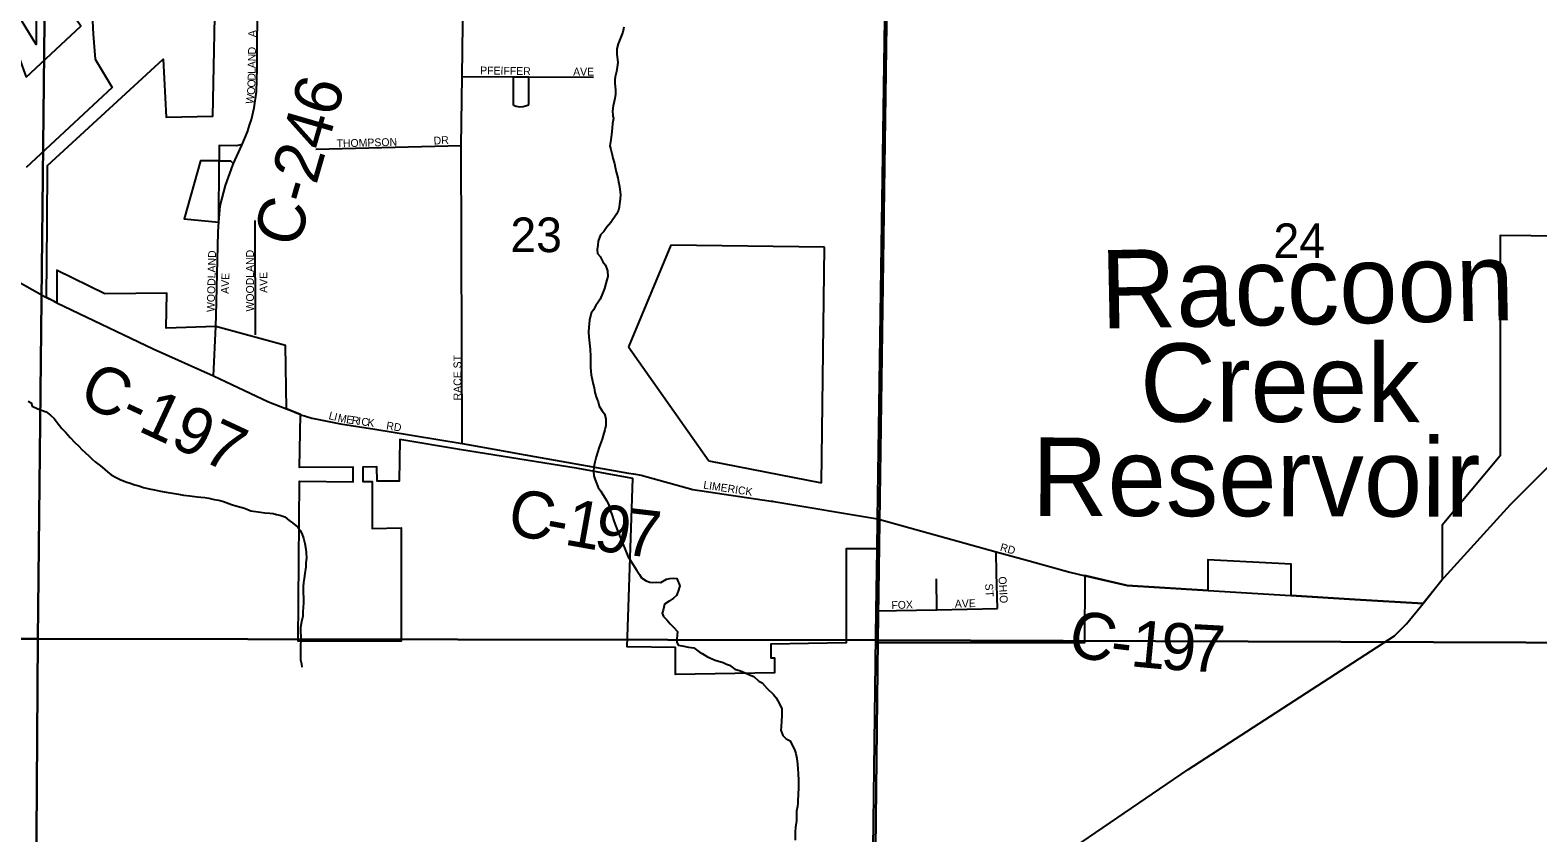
# Model space of a CAD drawing. Extents: x 1588073 to 2013523, y 1090242 to 1357120.
# Drawn here: x 1832450 to 1842074, y 1195862 to 1200987 of the extents above; entities that cross this region are included whole.
import ezdxf

# ---------------------------------------------------------------- set-up
doc = ezdxf.new("R2010")
doc.units = 0
for name, color, linetype in [('GM_X_City_Street', 7, 'Continuous'), ('GM_X_City_Street_Text', 7, 'Continuous'), ('GM_X_Corporation', 7, 'Continuous'), ('GM_X_County_Road', 7, 'Continuous'), ('GM_X_County_Road_Text', 7, 'Continuous'), ('GM_X_Minor_Lake', 7, 'Continuous'), ('GM_X_Minor_Lake_Text', 7, 'Continuous'), ('GM_X_Minor_River', 7, 'Continuous'), ('GM_X_Section', 7, 'Continuous'), ('GM_X_Section_Text', 7, 'Continuous'), ('GM_X_State_Route', 7, 'Continuous')]:
    doc.layers.add(name, color=color, linetype=linetype)

msp = doc.modelspace()

# ---------------------------------------------------------------- linework, layer by layer
at = {"layer": 'GM_X_City_Street'}
for points in [[(1835208.7, 1198346.8), (1835201.3, 1200250), (1835207.6, 1200690.1), (1835217.1, 1201360.9), (1835222.3, 1201732.4), (1835227.4, 1202091.9), (1835233.2, 1202502), (1835238.8, 1202901.4)], [(1833852.8, 1200385.8), (1833862.7, 1200416.5), (1833879.6, 1200491.6), (1833895.6, 1200593.8), (1833899, 1200744.9), (1833899.8, 1200949.3), (1833904.9, 1201146.1), (1833926.9, 1201323.4), (1833974.1, 1201521.3), (1834043.6, 1201650.5), (1834081.2, 1201768.3), (1834081.2, 1201844.7), (1834066.1, 1201951.3), (1834018.5, 1202030.2), (1833958.3, 1202119.2)], [(1835207.6, 1200690.1), (1835533.2, 1200688.6), (1835633.6, 1200688.1), (1836045.4, 1200686.3)], [(1835533.2, 1200688.6), (1835532.6, 1200509.7), (1835538.8, 1200505.9), (1835552.1, 1200501.9), (1835575, 1200497.5), (1835598.1, 1200498.3), (1835626, 1200506.7), (1835630.2, 1200510.3), (1835632.9, 1200515.7), (1835633.6, 1200688.1)], [(1834272.6, 1200226), (1835201.3, 1200250)], [(1833634.4, 1199096.7), (1833637.2, 1199165.8), (1833649.9, 1199697.9), (1833652.7, 1199732.1)], [(1833889.2, 1199042.5), (1833885.5, 1199770.6)], [(1832546.8, 1199284.3), (1832554.9, 1199279.8), (1832594.9, 1199259.7)], [(1834247.5, 1198509.5), (1834249.4, 1198508.9), (1834431, 1198474.3), (1834649.7, 1198438.8), (1834872, 1198402.3)], [(1835468.9, 1198300.5), (1835572.9, 1198282)], [(1836301.4, 1198153.3), (1836350.2, 1198145.8), (1836679.4, 1198054), (1837181.1, 1197979.8)], [(1837181.1, 1197979.8), (1837187.8, 1197978.8), (1837198.2, 1197977.2), (1837858.7, 1197867.1)], [(1837858.7, 1197867.1), (1838615.8, 1197657), (1838826.6, 1197598.5)], [(1838619.2, 1197520.8), (1838615.8, 1197657)], [(1838624.8, 1197293.9), (1838619.2, 1197520.8), (1838619.2, 1197520.8)], [(1838826.6, 1197598.5), (1838827.5, 1197598.3), (1839087.5, 1197526.1), (1839184.3, 1197503.5)], [(1838238, 1197286.3), (1838234.7, 1197484.8)], [(1837850.1, 1197278.6), (1838238, 1197286.3), (1838624.8, 1197293.9)]]:
    msp.add_lwpolyline(points, dxfattribs=at)
at = {"layer": 'GM_X_Corporation'}
for points in [[(1832833.2, 1201343.9), (1832853.3, 1200961.2), (1832864.5, 1200801.5), (1832972.7, 1200621.4), (1832424, 1200109.5)], [(1843215.9, 1199660.1), (1841834, 1199675.8), (1841834.2, 1198269.8), (1841462.6, 1197826.7), (1841462.7, 1197478), (1841341.2, 1197325.7), (1840905.6, 1197351.6), (1840498.9, 1197376.6), (1840498.9, 1197576.7), (1839966.9, 1197604.5), (1839966.9, 1197409.3), (1839452.1, 1197441), (1839182, 1197504.1), (1839179.5, 1197074.9), (1837847.5, 1197074.6), (1837858.7, 1197676.1), (1837658.7, 1197676.1), (1837658.7, 1197074.6), (1837178.8, 1197066.3), (1837178.8, 1196979.3), (1837200.8, 1196979.7), (1837200.8, 1196884.7), (1836568.9, 1196873.6), (1836568.9, 1197046.1), (1836260.2, 1197050.2), (1836297.6, 1198125.2), (1835947.8, 1198188.4), (1835191.6, 1198309.6), (1834809.8, 1198373.5), (1834804.6, 1198106.9), (1834664.4, 1198107.9), (1834663.8, 1198198), (1834573.9, 1198197.3), (1834573.9, 1198104.7), (1834633.9, 1198105.8), (1834633.9, 1197805.8), (1834818.9, 1197809), (1834818.9, 1197086.4), (1834160.3, 1197086.5), (1834168.8, 1198106.9), (1834512.9, 1198103.7), (1834512.9, 1198196.9), (1834169.5, 1198194.5), (1834176.1, 1198532), (1834086.6, 1198568.6), (1834079.7, 1198973.5), (1833634.3, 1199095.8), (1833317.6, 1199083.8), (1833322.3, 1199307.9), (1832927.4, 1199302.7), (1832622.5, 1199451.4), (1832619.4, 1199453.6), (1832621.1, 1199246.6), (1832554.9, 1199279.8), (1832558.1, 1199749.6), (1832560.7, 1200123.3), (1833298.3, 1200801), (1833317.5, 1200430.6), (1833617.1, 1200436.9), (1833628.3, 1201072.2)]]:
    msp.add_lwpolyline(points, dxfattribs=at)
for points in [[(1832423.9, 1200685.8), (1832772.9, 1201011.4), (1832617.7, 1201241.5), (1832487.6, 1201159.9), (1832487.6, 1200894.1), (1832371.6, 1201087.2), (1832253.6, 1201013.3), (1832380.5, 1200809.4)], [(1833656.7, 1200152.4), (1833728.5, 1200152), (1833748.9, 1200135.8), (1833804.4, 1200257.7), (1833766.6, 1200247.7), (1833657.2, 1200249.9)], [(1833656.7, 1200152.4), (1833538.2, 1200153), (1833432.2, 1199781.9), (1833655, 1199761.1)]]:
    msp.add_lwpolyline(points, close=True, dxfattribs=at)
at = {"layer": 'GM_X_County_Road'}
for points in [[(1833652.7, 1199732.1), (1833655, 1199761.1), (1833663.4, 1199864.2), (1833696.3, 1199994.3), (1833743.6, 1200124.3), (1833748.9, 1200135.8), (1833804.4, 1200257.7), (1833837.4, 1200337.9), (1833852.8, 1200385.8)], [(1831981.5, 1199600.3), (1832546.8, 1199284.3)], [(1832594.9, 1199259.7), (1832621.1, 1199246.6), (1833234.4, 1198953), (1833621.2, 1198779.1), (1833971.6, 1198614.4), (1834086.6, 1198568.6), (1834138.8, 1198547.7), (1834176.1, 1198532), (1834182.7, 1198529.2), (1834200.8, 1198523.7)], [(1841475.3, 1197491.8), (1841900, 1197959.3), (1842461.9, 1198522.6), (1843209.4, 1199147.7)], [(1833621.2, 1198779.1), (1833634.3, 1199095.8), (1833634.4, 1199096.7)], [(1834200.8, 1198523.7), (1834247.5, 1198509.5)], [(1834872, 1198402.3), (1834896.3, 1198398.3), (1835208.7, 1198346.8)], [(1835208.7, 1198346.8), (1835468.9, 1198300.5)], [(1835572.9, 1198282), (1836269, 1198158.2), (1836301.4, 1198153.3)], [(1839184.3, 1197503.5), (1839185.1, 1197503.3), (1839452.1, 1197441), (1839969.1, 1197409.2)], [(1841341.2, 1197325.8), (1841461.7, 1197476.9), (1841475.3, 1197491.8)], [(1837820.2, 1194917.3), (1838756.1, 1195525.3), (1839842.6, 1196266.5), (1841159.7, 1197119.2), (1841235, 1197196.6), (1841341.2, 1197325.8)], [(1839969.1, 1197409.2), (1840496.8, 1197376.7)], [(1840496.8, 1197376.7), (1840905.6, 1197351.5), (1841341.2, 1197325.8)]]:
    msp.add_lwpolyline(points, dxfattribs=at)
at = {"layer": 'GM_X_Minor_Lake'}
for p, q in [((1836540, 1199614.8), (1836269.7, 1198964.5)), ((1837520.7, 1199601.5), (1836540, 1199614.8)), ((1837500.4, 1198097.6), (1837520.7, 1199601.5)), ((1836269.7, 1198964.5), (1836783, 1198238.1)), ((1836783, 1198238.1), (1837500.4, 1198097.6))]:
    msp.add_line(p, q, dxfattribs=at)
at = {"layer": 'GM_X_Minor_River'}
for p, q in [((1837520.7, 1199601.5), (1837520.7, 1199601.5)), ((1836269.7, 1198964.5), (1836269.7, 1198964.5)), ((1836783, 1198238.1), (1836783, 1198238.1)), ((1837500.4, 1198097.6), (1837500.4, 1198097.6))]:
    msp.add_line(p, q, dxfattribs=at)
for points in [[(1836239.2, 1201006), (1836233.4, 1200973.8), (1836219.5, 1200941.7), (1836211.6, 1200921.6), (1836203.7, 1200899.5), (1836195.8, 1200867.4), (1836196, 1200833.3), (1836200.3, 1200781.1), (1836196.4, 1200751), (1836192.5, 1200722.9), (1836184.7, 1200688.8), (1836182.8, 1200668.7), (1836182.9, 1200646.7), (1836187.1, 1200606.6), (1836187.2, 1200578.5), (1836181.4, 1200550.4), (1836177.5, 1200530.3), (1836171.6, 1200504.2), (1836167.7, 1200472.1), (1836169.9, 1200442), (1836174, 1200422), (1836168.1, 1200389.9), (1836164.3, 1200361.8), (1836160.5, 1200319.6), (1836156.6, 1200287.5), (1836150.8, 1200247.4), (1836156.9, 1200225.4), (1836165.1, 1200191.3), (1836169.3, 1200169.3), (1836179.4, 1200135.2), (1836183.6, 1200111.2), (1836191.7, 1200081.1), (1836202, 1200043.1), (1836206.1, 1200019), (1836212.3, 1199989), (1836214.4, 1199968.9), (1836218.5, 1199936.8), (1836216.7, 1199906.7), (1836212.8, 1199878.6), (1836208.9, 1199856.6), (1836205, 1199836.5), (1836193.1, 1199812.4), (1836157.3, 1199758), (1836129.4, 1199725.8), (1836111.5, 1199701.7), (1836091.5, 1199679.5), (1836075.7, 1199639.3), (1836073.8, 1199613.2), (1836070, 1199587.1), (1836072.1, 1199561.1), (1836088.2, 1199541.1)], [(1836088.2, 1199541.1), (1836106.4, 1199507.1), (1836122.6, 1199487.1), (1836134.8, 1199449.1), (1836137, 1199415), (1836131.1, 1199392.9), (1836125.2, 1199368.8), (1836115.3, 1199336.6), (1836103.5, 1199304.5), (1836087.6, 1199270.3), (1836075.7, 1199250.2), (1836061.8, 1199228.1), (1836045.8, 1199201.9), (1836031.9, 1199179.8), (1836020.1, 1199135.6), (1836016.3, 1199091.5), (1836014.5, 1199059.4), (1836016.7, 1199027.3), (1836018.8, 1199007.2), (1836025.1, 1198949.1), (1836027.3, 1198903), (1836027.7, 1198832.8), (1836031.9, 1198786.7), (1836044.2, 1198726.6), (1836050.4, 1198702.5), (1836054.5, 1198672.4), (1836064.7, 1198640.4), (1836074.9, 1198614.4), (1836083, 1198586.3), (1836101.2, 1198556.3), (1836115.3, 1198536.3), (1836125.5, 1198506.3), (1836125.7, 1198462.2), (1836117.9, 1198434.1), (1836108, 1198399.9), (1836102.1, 1198375.8), (1836082.3, 1198323.6), (1836072.5, 1198289.4), (1836062.6, 1198263.3), (1836054.8, 1198229.2), (1836048.9, 1198199.1), (1836047, 1198169), (1836047.2, 1198140.9), (1836057.3, 1198114.9), (1836065.5, 1198094.8), (1836075.6, 1198066.8), (1836093.8, 1198042.8), (1836105.9, 1198022.8), (1836132.2, 1197982.8), (1836144.3, 1197954.8), (1836154.5, 1197914.8), (1836162.7, 1197894.7), (1836178.9, 1197848.7), (1836199.3, 1197792.6), (1836219.6, 1197738.6), (1836233.8, 1197706.5), (1836248, 1197670.5), (1836264.2, 1197628.5), (1836282.4, 1197600.5), (1836322.8, 1197536.5), (1836339, 1197510.5), (1836353.1, 1197490.5), (1836381.3, 1197470.6), (1836405.4, 1197462.7), (1836425.4, 1197460.8), (1836445.4, 1197462.8), (1836475.5, 1197461), (1836511.5, 1197481.2), (1836533.5, 1197485.3), (1836553.5, 1197487.4), (1836577.6, 1197485.5), (1836597.9, 1197439.5), (1836586, 1197405.3), (1836576.2, 1197377.2), (1836556.2, 1197361.1), (1836528.2, 1197340.9), (1836500.3, 1197322.7), (1836490.4, 1197284.6), (1836484.5, 1197264.5), (1836492.7, 1197242.4), (1836514.8, 1197222.5), (1836535, 1197196.5), (1836557.1, 1197174.6), (1836581.3, 1197148.6), (1836577.5, 1197100.4), (1836577.6, 1197080.4), (1836585.8, 1197060.4), (1836611.8, 1197056.5), (1836652, 1197048.6), (1836686.1, 1197042.8), (1836720.3, 1197016.9), (1836740.4, 1197006.9), (1836774.5, 1196985.1), (1836822.7, 1196965.2), (1836872.9, 1196949.4), (1836895, 1196939.5), (1836915.1, 1196931.6), (1836947.3, 1196907.6), (1836985.4, 1196895.8), (1837013.6, 1196883.9), (1837041.7, 1196870)], [(1832437.1, 1198619.1), (1832457.2, 1198607.1), (1832463.4, 1198587.1), (1832499.5, 1198569.2), (1832551.7, 1198549.4), (1832579.9, 1198529.5), (1832604.1, 1198507.5), (1832628.3, 1198473.5), (1832652.5, 1198443.6), (1832674.7, 1198419.6), (1832704.9, 1198385.7), (1832735.1, 1198353.7), (1832761.3, 1198329.8), (1832779.4, 1198309.8), (1832823.7, 1198269.9), (1832845.9, 1198247.9), (1832866, 1198230), (1832890.1, 1198212), (1832910.3, 1198196.1), (1832944.5, 1198166.2), (1832966.6, 1198148.2), (1832998.8, 1198130.3), (1833024.9, 1198118.4), (1833061.1, 1198102.5), (1833089.2, 1198094.7), (1833117.3, 1198084.8), (1833143.4, 1198076.9), (1833173.5, 1198067), (1833209.6, 1198059.1), (1833243.7, 1198051.3), (1833281.8, 1198043.4), (1833317.9, 1198037.6), (1833358.1, 1198029.8), (1833396.2, 1198023.9), (1833428.3, 1198018.1), (1833468.4, 1198014.2), (1833516.5, 1198006.4), (1833538.6, 1198004.5), (1833564.6, 1198002.7), (1833590.7, 1197998.8), (1833624.8, 1197990.9), (1833654.9, 1197985), (1833685, 1197977.2), (1833735.2, 1197959.3), (1833763.3, 1197949.5), (1833795.4, 1197941.6), (1833817.5, 1197935.7), (1833859.7, 1197917.8), (1833919.9, 1197910.1), (1833947.9, 1197904.2), (1833980, 1197902.3), (1834002.1, 1197900.5), (1834022.1, 1197894.5), (1834044.2, 1197890.6), (1834076.3, 1197878.8), (1834102.5, 1197856.8), (1834124.6, 1197840.9), (1834158.8, 1197813), (1834173, 1197793)], [(1834173, 1197793), (1834185.1, 1197773), (1834195.3, 1197742.9), (1834203.5, 1197708.9), (1834209.7, 1197672.8), (1834211.8, 1197650.7), (1834213.9, 1197616.7), (1834210.1, 1197586.6), (1834210.2, 1197560.5), (1834202.4, 1197518.3), (1834198.6, 1197486.2), (1834194.7, 1197460.1), (1834192.8, 1197432), (1834193, 1197397.9), (1834195.2, 1197357.8), (1834195.4, 1197327.7), (1834193.5, 1197303.7), (1834191.6, 1197273.6), (1834189.8, 1197245.5), (1834181.9, 1197209.3), (1834176.1, 1197173.2), (1834176.3, 1197139.1), (1834178.4, 1197119.1), (1834178.5, 1197095), (1834176.7, 1197056.9), (1834174.9, 1197020.8), (1834175.1, 1196966.6), (1834181.3, 1196940.6), (1834183.4, 1196920.5)], [(1837041.7, 1196870), (1837069.8, 1196860.1), (1837102, 1196830.2), (1837122.1, 1196820.2), (1837154.4, 1196784.3), (1837194.6, 1196746.4), (1837212.8, 1196724.4), (1837233, 1196686.4), (1837249.2, 1196654.4), (1837247.3, 1196628.3), (1837247.4, 1196608.2), (1837245.6, 1196578.1), (1837243.8, 1196540), (1837241.9, 1196517.9), (1837254.1, 1196483.9), (1837276.2, 1196461.9), (1837302.4, 1196450), (1837330.7, 1196388), (1837336.8, 1196368), (1837345, 1196335.9), (1837349.2, 1196299.8), (1837349.4, 1196269.7), (1837351.5, 1196243.7), (1837353.8, 1196193.5), (1837353.9, 1196157.4), (1837352.2, 1196101.3), (1837350.3, 1196073.2), (1837350.5, 1196051.1), (1837348.6, 1196031.1), (1837342.7, 1196000.9), (1837340.8, 1195980.9), (1837341, 1195938.8), (1837335.2, 1195898.6), (1837333.3, 1195868.5), (1837333.6, 1195816.4)]]:
    msp.add_lwpolyline(points, dxfattribs=at)
at = {"layer": 'GM_X_Section'}
for points in [[(1832556.3, 1202418.4), (1832498.9, 1197101.7), (1827295.7, 1197100.9), (1827365.2, 1202461.5)], [(1832556.3, 1202418.4), (1837935.3, 1202386.5), (1837861.8, 1197091.9), (1832498.9, 1197101.7)], [(1843258.1, 1202330.9), (1843180.8, 1197072.2), (1837861.8, 1197091.9), (1837935.3, 1202386.5)], [(1832498.9, 1197101.7), (1832463.2, 1191762.8), (1827254.8, 1191810.3), (1827295.7, 1197100.9)], [(1832498.9, 1197101.7), (1837861.8, 1197091.9), (1837802.1, 1191759.2), (1832463.2, 1191762.8)], [(1843180.8, 1197072.2), (1843101, 1191743.6), (1837802.1, 1191759.2), (1837861.8, 1197091.9)]]:
    msp.add_lwpolyline(points, close=True, dxfattribs=at)
at = {"layer": 'GM_X_State_Route'}
for points in [[(1837855.8, 1197671), (1837858.7, 1197867.1), (1837906.5, 1201059.9), (1837908.3, 1201180.2), (1837912.1, 1201429.6), (1837917.6, 1201799), (1837918.1, 1201829.3)], [(1837848.1, 1197117.6), (1837848.1, 1197117.7), (1837850.1, 1197278.6), (1837855.8, 1197671)], [(1837819.6, 1194864.5), (1837820.2, 1194917.3), (1837848.1, 1197117.6)]]:
    msp.add_lwpolyline(points, dxfattribs=at)

# ---------------------------------------------------------------- texts
at = {"layer": 'GM_X_City_Street_Text'}
for s, rotation, p in [('A', 88.3606, (1833891.3, 1200941.5)), ('D', 89.12565, (1833890.5, 1200831.2)), ('A', 89.13696, (1833889.2, 1200743.2)), ('N', 89.14751, (1833889.9, 1200787.2)), ('D', 89.15393, (1833888.1, 1200664)), ('L', 89.12573, (1833888.7, 1200708)), ('PFEIFFER', 359.0747, (1835322.1, 1200704.8)), ('AVE', 0.00001, (1835916, 1200696.1)), ('O', 84.71058, (1833883, 1200572)), ('O', 89.09193, (1833887.3, 1200620)), ('W', 81.17202, (1833873.9, 1200512.1)), ('THOMPSON', 1.50804, (1834406.5, 1200238.4)), ('DR', 3.01671, (1835026.7, 1200256)), ('WOODLAND', 88.60355, (1833627.4, 1199186.5)), ('WOODLAND', 90, (1833878.2, 1199190.6)), ('AVE', 88.02609, (1833717.7, 1199302.4)), ('AVE', 90, (1833964.2, 1199309.4)), ('RACE ST', 90, (1835202.5, 1198623)), ('L', 345.37395, (1834352, 1198504.5)), ('I', 345.36993, (1834386, 1198495.7)), ('M', 348.56046, (1834410.3, 1198489.4)), ('E', 351.82134, (1834465.1, 1198478.4)), ('R', 351.87337, (1834500, 1198473.4)), ('I', 351.86681, (1834539.2, 1198467.8)), ('C', 351.87337, (1834561, 1198464.7)), ('K', 351.86372, (1834600.2, 1198459.1)), ('RD', 351.02708, (1834720.6, 1198438.7)), ('LIMERICK', 351.3844, (1836744.6, 1198060.4)), ('RD', 344.47401, (1838637.7, 1197664.1)), ('ST', 273.57422, (1838545.5, 1197452.3)), ('OHIO', 273.26871, (1838631.3, 1197497.2)), ('FOX', 2.0443, (1837948.4, 1197290.4)), ('AVE', 1.9739, (1838353.2, 1197299.3))]:
    msp.add_text(s, height=50, rotation=rotation, dxfattribs=at).set_placement(p)
at = {"layer": 'GM_X_County_Road_Text'}
for s, rotation, p in [('C-246', 73.83089, (1834158.3, 1199587.5)), ('C-197', 335.03072, (1832746.6, 1198610.9)), ('C', 349.48273, (1835486.3, 1197771.8)), ('1', 349.92813, (1835852.2, 1197704.1)), ('9', 350.77572, (1836038.9, 1197670.9)), ('7', 353.27926, (1836235.5, 1197639.3)), ('-', 349.5795, (1835729.1, 1197726.7)), ('C', 346.53175, (1839059.8, 1197006.2)), ('1', 354.5927, (1839467.2, 1196926.3)), ('9', 356.36502, (1839661.2, 1196908.1)), ('7', 356.83033, (1839848.3, 1196896.2)), ('-', 353.0323, (1839336, 1196942.2))]:
    msp.add_text(s, height=300, rotation=rotation, dxfattribs=at).set_placement(p)
at = {"layer": 'GM_X_Minor_Lake_Text'}
for s, rotation, p in [('Raccoon', 1.17805, (1839286.3, 1199081.1)), ('Creek', 359.89584, (1839534.5, 1198487.2)), ('Reservoir', 359.89603, (1838844.2, 1197886.1))]:
    msp.add_text(s, height=500.26, rotation=rotation, dxfattribs=at).set_placement(p)
at = {"layer": 'GM_X_Section_Text'}
for s, p in [('23', (1835515.6, 1199569.4)), ('24', (1840386.4, 1199531.4))]:
    msp.add_text(s, height=221, rotation=0.00001, dxfattribs=at).set_placement(p)

doc.saveas('drawing.dxf')
